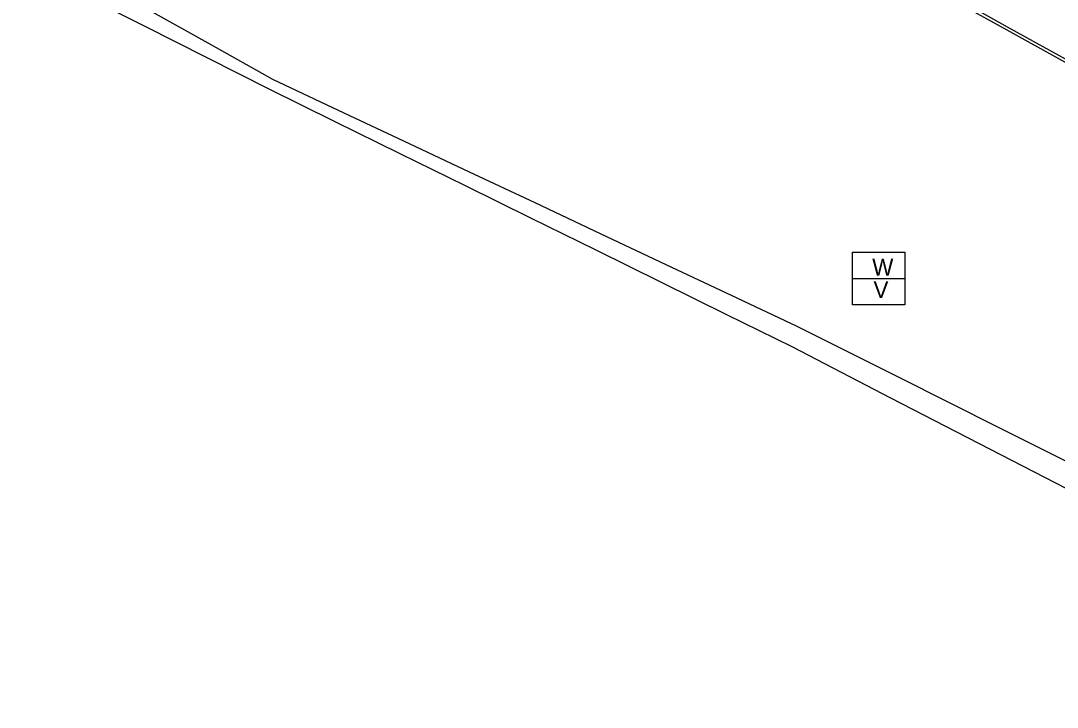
# Model space of a CAD drawing. Extents: x 1411444 to 1458157, y 300965 to 327300.
# Drawn here: x 1454871.1 to 1455057, y 302496.1 to 302619.4 of the extents above; entities that cross this region are included whole.
import ezdxf

# ---------------------------------------------------------------- set-up
doc = ezdxf.new("R2010")
doc.units = 0
for name, color, linetype in [('S_DITCHLINE', 7, 'Continuous'), ('S_EDGE_PAVEMENT', 7, 'Continuous'), ('S_SHOULDER', 7, 'Continuous'), ('S_WATER_UTILITIES', 7, 'Continuous')]:
    doc.layers.add(name, color=color, linetype=linetype)

msp = doc.modelspace()

# ---------------------------------------------------------------- linework, layer by layer
at = {"layer": 'S_DITCHLINE'}
for points in [[(1454871.95, 302633.66), (1454883.03, 302627.47), (1454894.11, 302621.28), (1454905.18, 302615.1), (1454916.26, 302608.91), (1454928.01, 302603.37), (1454939.77, 302597.83), (1454951.52, 302592.28), (1454963.28, 302586.74), (1454975.03, 302581.19), (1454986.79, 302575.65), (1454998.54, 302570.1), (1455010.3, 302564.56), (1455028.48, 302555.45), (1455046.66, 302546.34), (1455064.84, 302537.24), (1455083.02, 302528.13), (1455097.29, 302520.44), (1455111.57, 302512.75), (1455125.84, 302505.06), (1455140.12, 302497.37)], [(1454871.09, 302629.69), (1454893.36, 302618.43), (1454915.62, 302607.16), (1454927.34, 302601.38), (1454939.06, 302595.59), (1454950.79, 302589.81), (1454962.51, 302584.02), (1454974.23, 302578.24), (1454985.95, 302572.46), (1454997.67, 302566.67), (1455009.39, 302560.89), (1455027.12, 302551.71), (1455044.86, 302542.53), (1455062.59, 302533.36), (1455080.32, 302524.18), (1455095.14, 302517.17), (1455109.97, 302510.16), (1455124.79, 302503.15), (1455139.61, 302496.15)]]:
    msp.add_lwpolyline(points, dxfattribs=at)
at = {"layer": 'S_EDGE_PAVEMENT'}
msp.add_lwpolyline([(1454925.81, 302685.46), (1454941.53, 302677.1), (1454957.26, 302668.74), (1454970.34, 302661.62), (1454983.42, 302654.5), (1454998.88, 302645.92), (1455014.34, 302637.35), (1455031.19, 302627.81), (1455048.04, 302618.28), (1455067.2, 302607.72), (1455069.22, 302606.61)], dxfattribs=at)
at = {"layer": 'S_SHOULDER'}
msp.add_lwpolyline([(1454925.29, 302684.5), (1454940.65, 302675.41), (1454956.01, 302666.32), (1454967.74, 302659.95), (1454979.48, 302653.58), (1454982.92, 302653.42), (1454998.43, 302645.04), (1455013.94, 302636.66), (1455030.95, 302627.2), (1455047.95, 302617.74), (1455067.03, 302607.19), (1455068.95, 302606.13)], dxfattribs=at)
at = {"layer": 'S_WATER_UTILITIES'}
for p, q in [((1455020.27, 302577.82), (1455029.68, 302577.82)), ((1455020.27, 302568.4), (1455020.27, 302577.82)), ((1455029.68, 302577.82), (1455029.68, 302568.4)), ((1455020.27, 302573.13), (1455029.68, 302573.13)), ((1455029.68, 302568.4), (1455020.27, 302568.4))]:
    msp.add_line(p, q, dxfattribs=at)

# ---------------------------------------------------------------- texts
for s, p in [('W', (1455023.82, 302573.66)), ('V', (1455024.05, 302569.6))]:
    msp.add_text(s, height=3, rotation=360, dxfattribs=at).set_placement(p)

doc.saveas('drawing.dxf')
